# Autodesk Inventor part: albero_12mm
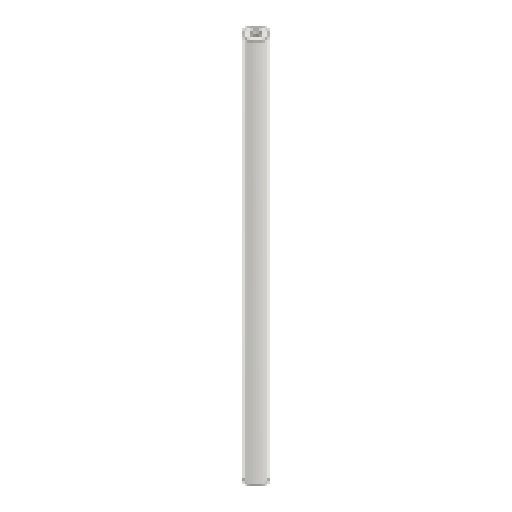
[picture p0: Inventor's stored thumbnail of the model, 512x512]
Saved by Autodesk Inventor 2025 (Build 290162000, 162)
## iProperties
Created: 2025-04
Part Number: albero_12mm
Material: Generico
Document SubType Name: Modeling
Designer: R5800u
Density: 1 g/cm^3
Appearance: Acciaio
Author: R5800u
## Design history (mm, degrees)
sketch "Schizzo1"
  geometry: C1 r 2.5 at (0, 0); C2 r 1 at (0, 0); 1 further point
  constraints: 2 centre point, 1 coincident
  dimensions: "d0" = 5 diameter of C1; "d1" = 1.5 radial gap between concentric circles of C1 C2
extrude "Estrusione1" new body sketch "Schizzo1" distance "d2" = 100.2; taper "d3" = 0 deg
node "Solido1"
